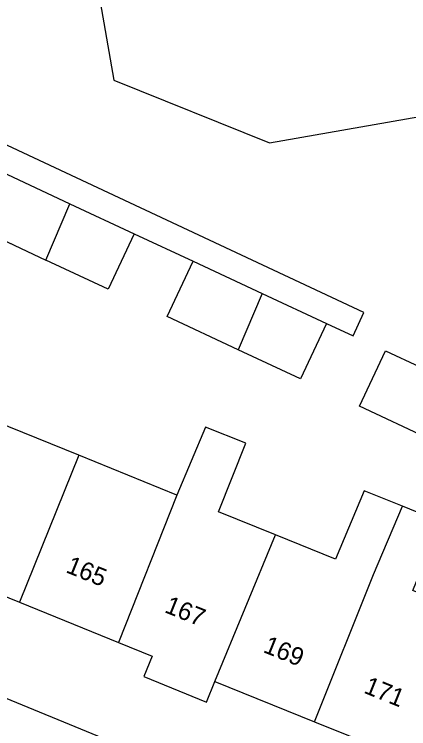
# Model space of a CAD drawing. Extents: x 162880 to 165536, y 384011 to 385179.
# Drawn here: x 163905.09 to 163927.09, y 384549.32 to 384589.16 of the extents above; entities that cross this region are included whole.
import ezdxf

# ---------------------------------------------------------------- set-up
doc = ezdxf.new("R2010")
doc.units = 0
for name, color, linetype in [('IMGEO_Pand', 7, 'Continuous'), ('IMGEO_Pand_nummerreeks', 7, 'Continuous'), ('IMGEO_Voetpad_open', 7, 'Continuous')]:
    doc.layers.add(name, color=color, linetype=linetype)

msp = doc.modelspace()

# ---------------------------------------------------------------- linework, layer by layer
at = {"layer": 'IMGEO_Pand'}
for points in [[(163908.865, 384595.738), (163910.653, 384585.499), (163919.328, 384581.993), (163946.296, 384586.722)], [(163904.313, 384580.316), (163902.903, 384577.305), (163906.861, 384575.451)], [(163904.313, 384580.316), (163904.352, 384580.398), (163908.188, 384578.601)], [(163906.861, 384575.451), (163908.188, 384578.601)], [(163908.188, 384578.601), (163911.774, 384576.922)], [(163911.774, 384576.922), (163910.325, 384573.828), (163906.861, 384575.451)], [(163917.584, 384570.451), (163913.629, 384572.303), (163915.078, 384575.396)], [(163915.078, 384575.396), (163918.913, 384573.6)], [(163918.913, 384573.6), (163917.584, 384570.451)], [(163918.913, 384573.6), (163922.5, 384571.92)], [(163922.5, 384571.92), (163921.051, 384568.826), (163917.584, 384570.451)], [(163928.304, 384565.452), (163924.342, 384567.308), (163925.791, 384570.401), (163929.628, 384568.604)], [(163908.684, 384564.569), (163903.211, 384566.783)], [(163919.656, 384560.13), (163916.474, 384561.418), (163918.009, 384565.237), (163915.764, 384566.14), (163914.165, 384562.352)], [(163908.684, 384564.569), (163905.375, 384556.372)], [(163914.165, 384562.352), (163908.684, 384564.569)], [(163914.165, 384562.352), (163910.9, 384554.136)], [(163926.739, 384561.726), (163924.609, 384562.583), (163923.009, 384558.774), (163919.656, 384560.13)], [(163921.843, 384549.709), (163927.426, 384547.45), (163929.302, 384552.085), (163930.742, 384555.645), (163927.323, 384557.028), (163928.876, 384560.867), (163926.739, 384561.726)], [(163921.843, 384549.709), (163925.137, 384557.913), (163926.739, 384561.726)], [(163916.286, 384551.957), (163919.656, 384560.13)], [(163899.913, 384558.582), (163905.375, 384556.372)], [(163905.375, 384556.372), (163910.9, 384554.136)], [(163910.9, 384554.136), (163912.783, 384553.374), (163912.323, 384552.237), (163915.818, 384550.801), (163916.286, 384551.957)], [(163916.286, 384551.957), (163921.843, 384549.709)]]:
    msp.add_lwpolyline(points, dxfattribs=at)
at = {"layer": 'IMGEO_Voetpad_open'}
for points in [[(163922.5, 384571.92), (163923.987, 384571.223), (163924.597, 384572.526), (163891.92, 384587.83)], [(163911.774, 384576.922), (163915.078, 384575.396)], [(163919.013, 384545.096), (163886.689, 384558.39)]]:
    msp.add_lwpolyline(points, dxfattribs=at)

# ---------------------------------------------------------------- texts
at = {"layer": 'IMGEO_Pand_nummerreeks'}
for s, p in [('165', (163907.916, 384558.062)), ('167', (163913.419, 384555.835)), ('169', (163918.923, 384553.608)), ('171', (163924.532, 384551.34))]:
    msp.add_text(s, height=1, rotation=337.9728, dxfattribs=at).set_placement(p)

doc.saveas('drawing.dxf')
